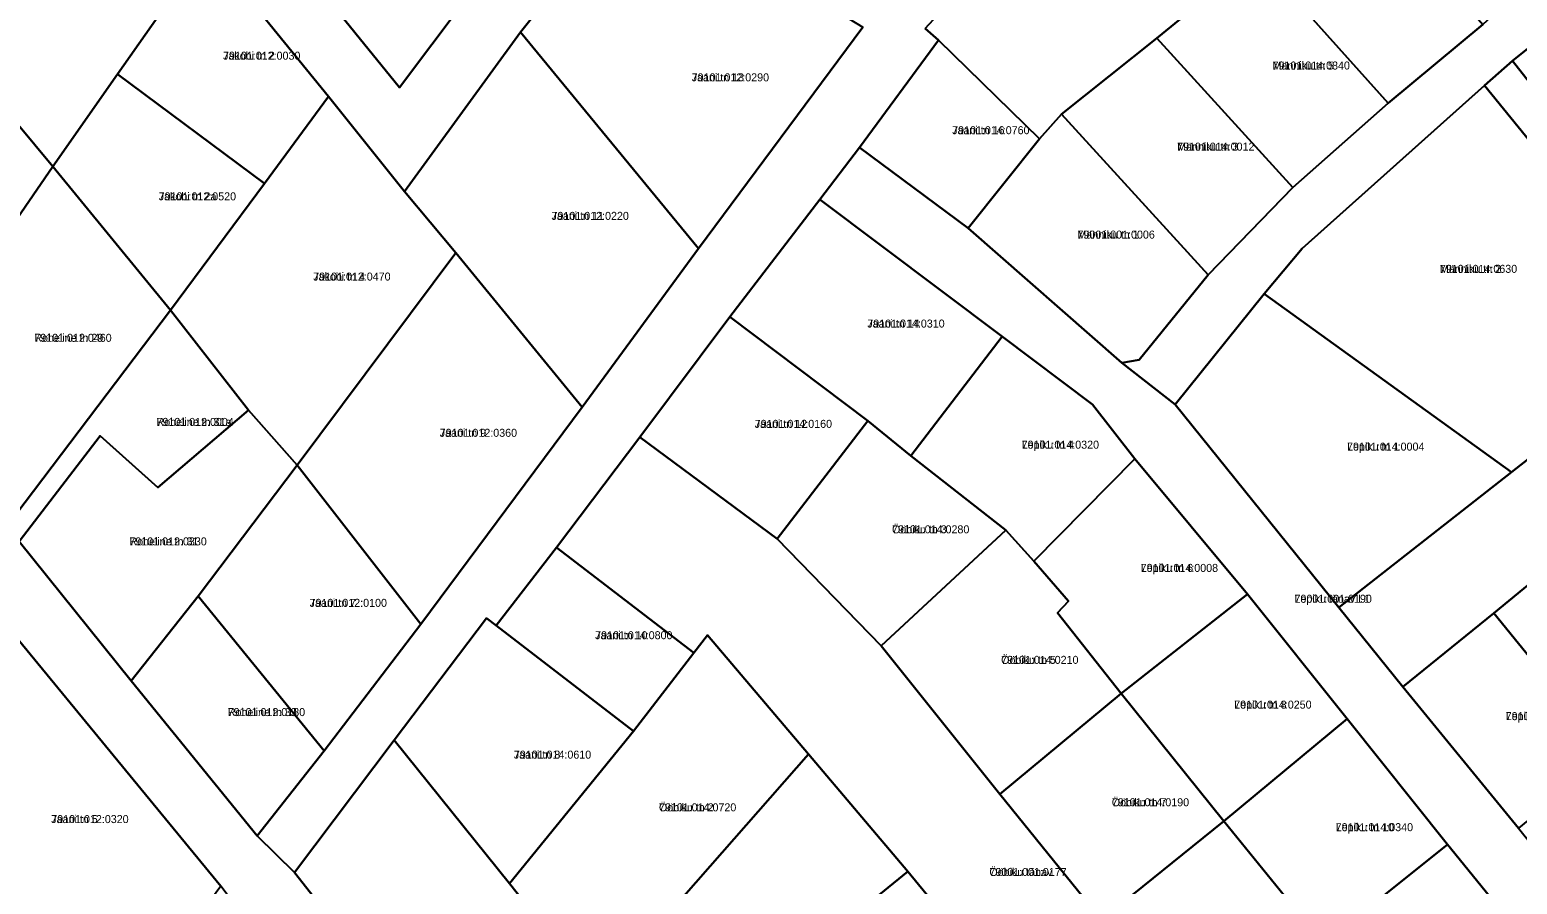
# Model space of a CAD drawing. Extents: x 587616 to 632239, y 6547421 to 6574977.
# Drawn here: x 612323.4 to 612602.3, y 6570550.5 to 6570710.7 of the extents above; entities that cross this region are included whole.
import ezdxf

# ---------------------------------------------------------------- set-up
doc = ezdxf.new("R2010")
doc.units = 0
for name, color, linetype in [('L_AADRESS', 7, 'Continuous'), ('PIIR', 7, 'Continuous'), ('TUNNUS', 7, 'Continuous')]:
    doc.layers.add(name, color=color, linetype=linetype)

msp = doc.modelspace()

# ---------------------------------------------------------------- linework, layer by layer
at = {"layer": 'PIIR'}
for points in [[(612356.6, 6570726.21), (612339.86, 6570702.31), (612327.72, 6570685), (612317.22, 6570697.55), (612283.5, 6570670.85), (612281.63, 6570667.58), (612281.6, 6570663.77), (612269.61, 6570677.95), (612292.21, 6570694.33), (612401.38, 6570781.15)], [(612436.8, 6570737.15), (612415.41, 6570710.19), (612393.64, 6570680.31), (612379.4, 6570698.14), (612356.6, 6570726.21)], [(612367.62, 6570730.85), (612392.69, 6570699.82), (612410.73, 6570723.8)], [(612619.25, 6570719.17), (612601.37, 6570704.8), (612596.12, 6570700.23), (612561.96, 6570669.67), (612554.84, 6570661.14), (612538.11, 6570640.38), (612528.11, 6570648.18), (612531.38, 6570648.78), (612544.3, 6570664.7), (612560.16, 6570681.11), (612578.05, 6570696.88), (612595.82, 6570711.62), (612613.91, 6570728.5)], [(612491.29, 6570710.9), (612493.77, 6570708.69), (612478.97, 6570688.58), (612471.53, 6570678.85), (612454.66, 6570656.82), (612437.77, 6570634.29), (612422.16, 6570613.6), (612410.85, 6570598.94), (612409.02, 6570600.33), (612391.73, 6570577.49), (612373.01, 6570552.66), (612366.02, 6570559.5), (612378.62, 6570575.49), (612396.72, 6570599.19), (612426.95, 6570639.87), (612448.78, 6570669.63), (612479.57, 6570711.12)], [(612321.39, 6570614.7), (612342.43, 6570588.6), (612366.02, 6570559.5), (612373.01, 6570552.66), (612409.94, 6570505.71), (612413.89, 6570501.02), (612430.6, 6570480.58), (612449.59, 6570457.37), (612468.7, 6570434.03), (612487.82, 6570410.53), (612506.38, 6570387.66), (612496.97, 6570379.74), (612482.71, 6570397.51), (612469.71, 6570413.34), (612456.43, 6570429.69), (612442.99, 6570446.46), (612424.48, 6570469.13), (612402.3, 6570496.37), (612385.75, 6570516.7), (612382.23, 6570520.99), (612366.46, 6570540.5), (612359.19, 6570550.12), (612320.6, 6570597.07)]]:
    msp.add_lwpolyline(points, dxfattribs=at)
for points in [[(612551.19, 6570722.55), (612529.34, 6570748.14), (612549.18, 6570764.99), (612595.82, 6570711.62), (612578.05, 6570696.88), (612553.56, 6570724.29)], [(612386.15, 6570753.47), (612410.73, 6570723.8), (612392.69, 6570699.82), (612367.62, 6570730.85)], [(612491.29, 6570710.9), (612510.72, 6570731.98), (612529.34, 6570748.14), (612551.19, 6570722.55), (612534.7, 6570709.05), (612516.82, 6570694.83), (612512.72, 6570690.2), (612493.77, 6570708.69)], [(612436.8, 6570737.15), (612446.97, 6570731.09), (612479.57, 6570711.12), (612448.78, 6570669.63), (612415.41, 6570710.19)], [(612379.4, 6570698.14), (612367.43, 6570681.8), (612339.86, 6570702.31), (612356.6, 6570726.21)], [(612551.19, 6570722.55), (612553.56, 6570724.29), (612578.05, 6570696.88), (612560.16, 6570681.11), (612534.7, 6570709.05)], [(612601.37, 6570704.8), (612619.25, 6570719.17), (612637.83, 6570696.01), (612622.43, 6570683.68), (612619.69, 6570681.49)], [(612393.64, 6570680.31), (612415.41, 6570710.19), (612448.78, 6570669.63), (612426.95, 6570639.87), (612403.28, 6570668.81)], [(612493.77, 6570708.69), (612512.72, 6570690.2), (612499.31, 6570673.44), (612478.97, 6570688.58)], [(612516.82, 6570694.83), (612534.7, 6570709.05), (612560.16, 6570681.11), (612544.3, 6570664.71), (612539.14, 6570670.38)], [(612606.48, 6570660.98), (612619.43, 6570671.56), (612596.12, 6570700.23), (612601.37, 6570704.8), (612619.69, 6570681.49), (612622.43, 6570683.68), (612641.31, 6570660.3), (612620.64, 6570642.98)], [(612339.86, 6570702.31), (612367.43, 6570681.8), (612349.8, 6570658.05), (612327.72, 6570685)], [(612364.42, 6570639.35), (612349.8, 6570658.05), (612367.43, 6570681.8), (612379.4, 6570698.14), (612393.64, 6570680.31), (612403.28, 6570668.81), (612373.54, 6570629.01)], [(612601.19, 6570627.73), (612554.84, 6570661.14), (612561.96, 6570669.67), (612596.12, 6570700.23), (612619.43, 6570671.56), (612606.48, 6570660.98), (612620.64, 6570642.98)], [(612568.81, 6570602.35), (612601.19, 6570627.73), (612620.64, 6570642.98), (612641.31, 6570660.3), (612656.86, 6570672.87), (612672.71, 6570685.64), (612688.34, 6570698.12), (612699.21, 6570683.77), (612678.15, 6570666.25), (612656.78, 6570649.18), (612648.77, 6570642.62), (612631.73, 6570628.89), (612614.73, 6570615.16), (612597.86, 6570601.3), (612580.82, 6570587.48)], [(612281.6, 6570663.77), (612281.63, 6570667.58), (612283.5, 6570670.85), (612317.22, 6570697.55), (612327.72, 6570685), (612298.7, 6570642.82), (612283.48, 6570661.56)], [(612512.72, 6570690.2), (612516.82, 6570694.83), (612539.14, 6570670.38), (612544.3, 6570664.7), (612531.38, 6570648.78), (612528.11, 6570648.18), (612499.31, 6570673.44)], [(612639.61, 6570495.79), (612627.14, 6570511.23), (612608.16, 6570534.51), (612589.19, 6570557.93), (612570.4, 6570581.47), (612551.7, 6570604.82), (612530.58, 6570630.22), (612522.61, 6570640.4), (612505.68, 6570653.17), (612471.53, 6570678.85), (612478.97, 6570688.58), (612499.31, 6570673.44), (612528.11, 6570648.18), (612538.11, 6570640.38), (612568.81, 6570602.35), (612580.82, 6570587.48), (612602.49, 6570560.97), (612615.08, 6570545.35), (612627.71, 6570530.02), (612649.48, 6570503.22)], [(612327.72, 6570685), (612349.8, 6570658.05), (612319.02, 6570617.45), (612298.7, 6570642.82)], [(612488.59, 6570630.78), (612480.53, 6570637.31), (612454.66, 6570656.82), (612471.53, 6570678.85), (612505.68, 6570653.17)], [(612373.54, 6570629.01), (612403.28, 6570668.81), (612426.95, 6570639.87), (612396.72, 6570599.19)], [(612568.81, 6570602.35), (612538.11, 6570640.38), (612554.84, 6570661.14), (612601.19, 6570627.73)], [(612319.02, 6570617.45), (612349.8, 6570658.05), (612364.42, 6570639.35), (612347.39, 6570624.85), (612336.59, 6570634.5), (612321.39, 6570614.7)], [(612454.66, 6570656.82), (612480.53, 6570637.31), (612463.51, 6570615.22), (612437.77, 6570634.29)], [(612488.59, 6570630.78), (612505.68, 6570653.17), (612522.61, 6570640.4), (612530.58, 6570630.22), (612511.63, 6570611.04), (612506.4, 6570616.81)], [(612321.39, 6570614.7), (612336.59, 6570634.5), (612347.39, 6570624.85), (612364.42, 6570639.35), (612373.54, 6570629.01), (612354.99, 6570604.46), (612342.43, 6570588.6)], [(612463.51, 6570615.22), (612480.53, 6570637.31), (612488.59, 6570630.78), (612506.4, 6570616.81), (612483.01, 6570595.16)], [(612447.92, 6570593.85), (612422.16, 6570613.6), (612437.77, 6570634.29), (612463.51, 6570615.22), (612483.01, 6570595.16), (612505.23, 6570567.34), (612524.3, 6570543.79), (612542.99, 6570520.86), (612568.33, 6570489.4), (612560.18, 6570482.76), (612584.42, 6570452.32), (612575.81, 6570445.21), (612551.11, 6570475.57), (612538.51, 6570490.8), (612520.83, 6570512.64), (612501.76, 6570536.12), (612488.02, 6570552.83), (612469.38, 6570574.82), (612450.44, 6570597.17)], [(612373.54, 6570629.01), (612396.72, 6570599.19), (612378.62, 6570575.49), (612354.99, 6570604.46)], [(612530.58, 6570630.22), (612551.7, 6570604.82), (612528, 6570586.24), (612516.04, 6570601.35), (612518.13, 6570603.5), (612511.63, 6570611.04)], [(612483.01, 6570595.16), (612506.4, 6570616.81), (612511.63, 6570611.04), (612518.13, 6570603.5), (612516.04, 6570601.35), (612528, 6570586.24), (612505.23, 6570567.34)], [(612614.73, 6570615.16), (612636.42, 6570588.46), (612619.38, 6570574.83), (612597.86, 6570601.3)], [(612422.16, 6570613.6), (612447.92, 6570593.85), (612436.57, 6570579.17), (612410.85, 6570598.94)], [(612354.99, 6570604.46), (612378.62, 6570575.49), (612366.02, 6570559.5), (612342.43, 6570588.6)], [(612528, 6570586.24), (612551.7, 6570604.82), (612570.4, 6570581.47), (612547.26, 6570562.3)], [(612597.86, 6570601.3), (612619.38, 6570574.83), (612602.49, 6570560.97), (612580.82, 6570587.48)], [(612391.73, 6570577.49), (612409.02, 6570600.33), (612410.85, 6570598.94), (612436.57, 6570579.17), (612413.31, 6570550.56)], [(612339.15, 6570522.88), (612312.79, 6570550.34), (612295.67, 6570565.84), (612320.6, 6570597.07), (612359.19, 6570550.12)], [(612413.31, 6570550.56), (612436.57, 6570579.17), (612447.92, 6570593.85), (612450.44, 6570597.17), (612469.38, 6570574.82), (612429.81, 6570529.75)], [(612505.23, 6570567.34), (612528, 6570586.24), (612547.26, 6570562.3), (612524.3, 6570543.79)], [(612570.4, 6570581.47), (612589.19, 6570557.93), (612565.91, 6570539.27), (612547.26, 6570562.3)], [(612391.73, 6570577.49), (612413.31, 6570550.56), (612429.81, 6570529.75), (612409.94, 6570505.71), (612373.01, 6570552.66)], [(612429.81, 6570529.75), (612469.38, 6570574.82), (612488.02, 6570552.83), (612442.67, 6570515.9)], [(612524.3, 6570543.79), (612547.26, 6570562.3), (612565.91, 6570539.27), (612542.99, 6570520.86)], [(612565.91, 6570539.27), (612589.19, 6570557.93), (612608.16, 6570534.51), (612585.12, 6570515.56)], [(612453.81, 6570499.2), (612435.1, 6570521.61), (612413.89, 6570501.02), (612409.94, 6570505.71), (612429.81, 6570529.75), (612442.67, 6570515.9), (612488.02, 6570552.83), (612501.76, 6570536.12)]]:
    msp.add_lwpolyline(points, close=True, dxfattribs=at)

# ---------------------------------------------------------------- texts
at = {"layer": 'L_AADRESS'}
for s, p in [('Jakobi tn 2', (612359.63, 6570705.04)), ('Männiku tn 5', (612556.38, 6570703.2)), ('Jaani tn 13', (612447.49, 6570700.98)), ('Jaani tn 16', (612496.32, 6570691.07)), ('Männiku tn 3', (612538.49, 6570687.99)), ('Jakobi tn 2a', (612347.57, 6570678.67)), ('Jaani tn 11', (612421.21, 6570675.01)), ('Männiku tn 1', (612519.81, 6570671.5)), ('Jakobi tn 4', (612376.54, 6570663.63)), ('Männiku tn 2', (612587.74, 6570665.08)), ('Jaani tn 14', (612480.41, 6570654.82)), ('Roheline tn 29', (612324.25, 6570652.15)), ('Roheline tn 31a', (612347.15, 6570636.38)), ('Jaani tn 12', (612459.3, 6570636.02)), ('Jaani tn 9', (612400.25, 6570634.34)), ('Lepiku tn 4', (612509.35, 6570632.11)), ('Lepiku tn 1', (612570.35, 6570631.75)), ('Ööbiku tn 3', (612485.04, 6570616.24)), ('Roheline tn 31', (612342.08, 6570613.98)), ('Lepiku tn 6', (612531.67, 6570609.01)), ('Jaani tn 7', (612375.86, 6570602.46)), ('Lepiku tänav L1', (612560.5, 6570603.23)), ('Jaani tn 10', (612429.39, 6570596.39)), ('Ööbiku tn 5', (612505.5, 6570591.77)), ('Lepiku tn 8', (612549.2, 6570583.38)), ('Roheline tn 33', (612360.52, 6570581.98)), ('Lepiku tn 5', (612600.1, 6570581.22)), ('Jaani tn 8', (612414.15, 6570574)), ('Ööbiku tn 2', (612441.35, 6570564.12)), ('Ööbiku tn 7', (612526.24, 6570565.07)), ('Jaani tn 5', (612327.43, 6570561.92)), ('Lepiku tn 10', (612568.22, 6570560.4)), ('Ööbiku tänav', (612503.29, 6570552))]:
    msp.add_text(s, height=1.5, dxfattribs=at).set_placement(p)
at = {"layer": 'TUNNUS'}
for s, p in [('79101:012:0030', (612359.63, 6570705.04)), ('79101:014:0840', (612556.38, 6570703.2)), ('79101:012:0290', (612447.49, 6570700.98)), ('79101:014:0760', (612496.32, 6570691.07)), ('79101:014:0012', (612538.49, 6570687.99)), ('79101:012:0520', (612347.57, 6570678.67)), ('79101:012:0220', (612421.21, 6570675.01)), ('79001:001:0006', (612519.81, 6570671.5)), ('79101:012:0470', (612376.54, 6570663.63)), ('79101:014:0630', (612587.74, 6570665.08)), ('79101:014:0310', (612480.41, 6570654.82)), ('79101:012:0460', (612324.25, 6570652.15)), ('79101:012:0004', (612347.15, 6570636.38)), ('79101:014:0160', (612459.3, 6570636.02)), ('79101:012:0360', (612400.25, 6570634.34)), ('79101:014:0320', (612509.35, 6570632.11)), ('79101:014:0004', (612570.35, 6570631.75)), ('79101:014:0280', (612485.04, 6570616.24)), ('79101:012:0330', (612342.08, 6570613.98)), ('79101:014:0008', (612531.67, 6570609.01)), ('79101:012:0100', (612375.86, 6570602.46)), ('79001:001:0190', (612560.5, 6570603.23)), ('79101:014:0800', (612429.39, 6570596.39)), ('79101:014:0210', (612505.5, 6570591.77)), ('79101:014:0250', (612549.2, 6570583.38)), ('79101:012:0180', (612360.52, 6570581.98)), ('79101:014:0170', (612600.1, 6570581.22)), ('79101:014:0610', (612414.15, 6570574)), ('79101:014:0720', (612441.35, 6570564.12)), ('79101:014:0190', (612526.24, 6570565.07)), ('79101:012:0320', (612327.43, 6570561.92)), ('79101:014:0340', (612568.22, 6570560.4)), ('79001:001:0177', (612503.29, 6570552))]:
    msp.add_text(s, height=1.5, dxfattribs=at).set_placement(p)

doc.saveas('drawing.dxf')
